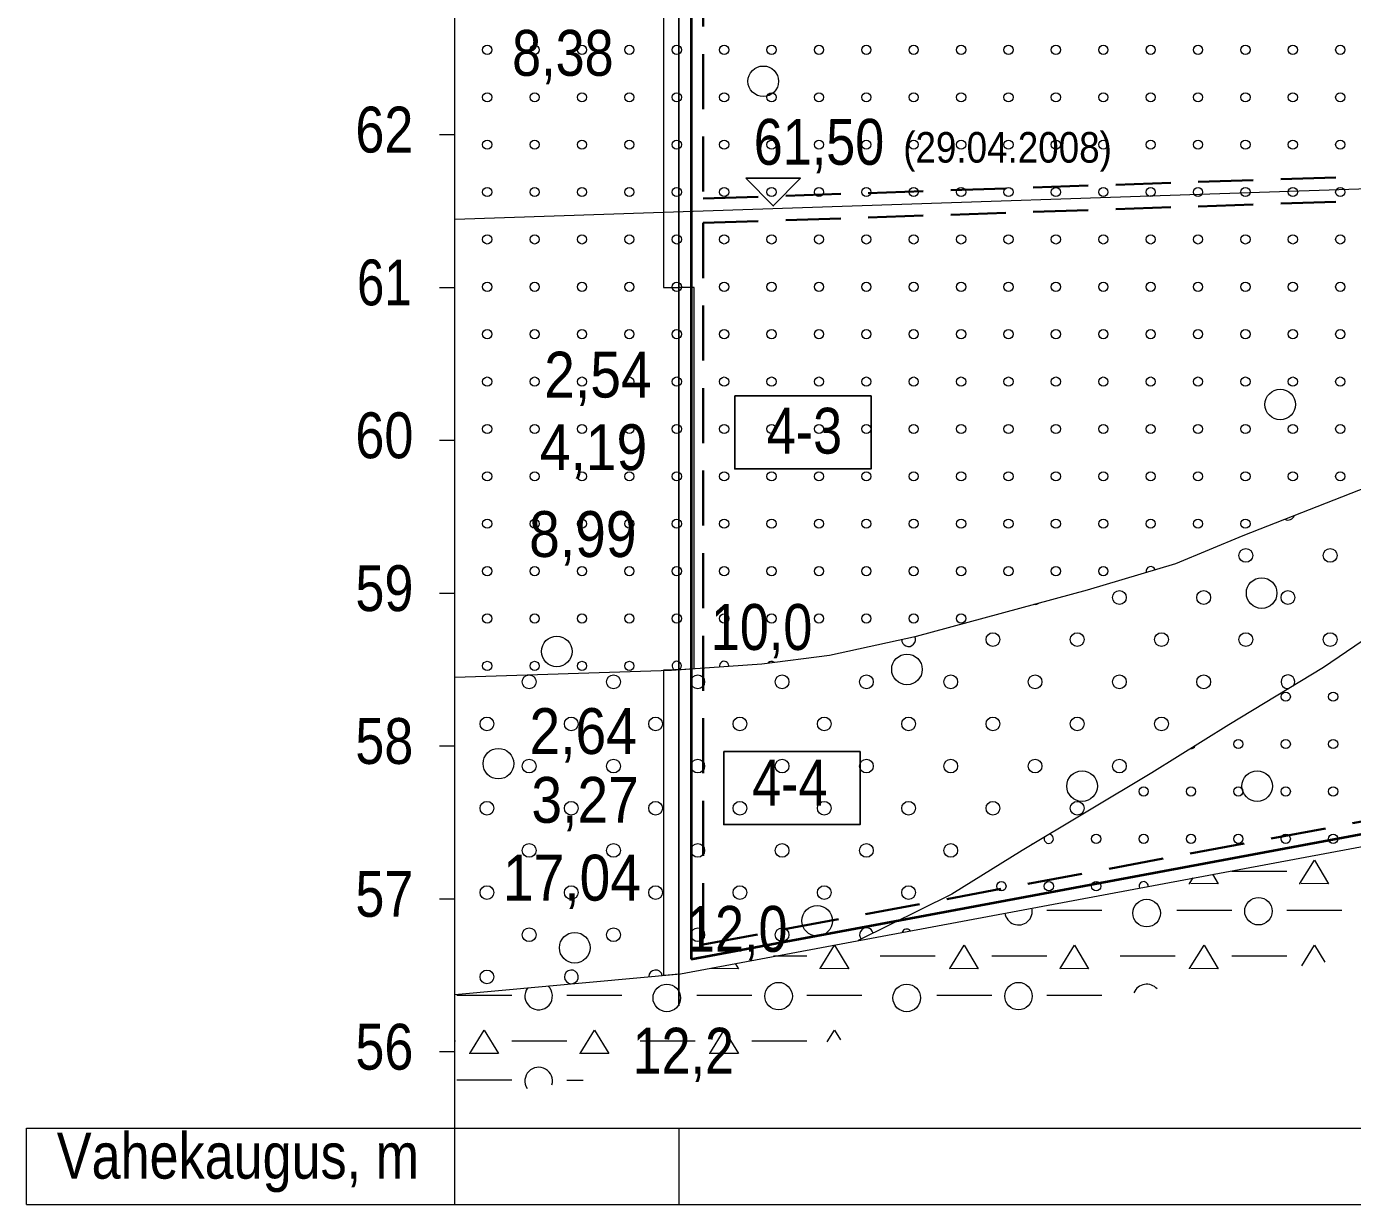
# Model space of a CAD drawing. Extents: x 640121 to 640955, y 6441885 to 6442246.
# Drawn here: x 640607 to 640693.8, y 6442062.2 to 6442139.2 of the extents above; entities that cross this region are included whole.
import ezdxf
from ezdxf.enums import TextEntityAlignment as Align

# ---------------------------------------------------------------- set-up
doc = ezdxf.new("R2010")
doc.units = 0
doc.header["$LTSCALE"] = 1.2
doc.linetypes.add('MEDIUM_DASHED', pattern=[4.5, 3, -1.5])
for name, color, linetype, lineweight in [('30', 7, 'Continuous', 13), ('31', 7, 'Continuous', 13), ('32', 7, 'Continuous', 13), ('33', 7, 'Continuous', 13), ('34', 7, 'Continuous', 25), ('35', 7, 'Continuous', 35), ('42', 7, 'Continuous', 13), ('43', 7, 'Continuous', 13), ('46', 7, 'Continuous', 13), ('47', 7, 'Continuous', 13)]:
    doc.layers.add(name, color=color, linetype=linetype, lineweight=lineweight)

msp = doc.modelspace()

# ---------------------------------------------------------------- linework, layer by layer
at = {"layer": '30'}
for p, q in [((640635.03, 6442062.16), (640635.03, 6442212.16)), ((640634.03, 6442132.16), (640635.03, 6442132.16)), ((640634.03, 6442122.16), (640635.03, 6442122.16)), ((640634.03, 6442112.16), (640635.03, 6442112.16)), ((640634.03, 6442102.16), (640635.03, 6442102.16)), ((640634.03, 6442092.16), (640635.03, 6442092.16)), ((640634.03, 6442082.16), (640635.03, 6442082.16)), ((640634.03, 6442072.16), (640635.03, 6442072.16)), ((640649.69, 6442067.16), (640649.69, 6442062.16)), ((640607.02, 6442062.16), (640933.07, 6442062.16))]:
    msp.add_line(p, q, dxfattribs=at)
msp.add_lwpolyline([(640607.02, 6442062.16), (640607.02, 6442067.16), (640933.07, 6442067.16)], dxfattribs=at)
at = {"layer": '31'}
for points in [[(640768.87, 6442162.69), (640757.51, 6442156.14), (640750.7, 6442151.38), (640740.57, 6442142.18), (640734.45, 6442136.52), (640730.23, 6442132.58), (640726.39, 6442128.73), (640721.62, 6442123.48), (640717.7, 6442119.38), (640711.91, 6442113.06), (640707.64, 6442108.99), (640702.12, 6442104.54), (640697.95, 6442101.43), (640691.86, 6442097.28), (640685.68, 6442093.53), (640680.63, 6442090.4), (640672.14, 6442085.32), (640667.54, 6442082.46), (640661.43, 6442079.43)], [(640635.03, 6442075.9), (640649.8, 6442077.26), (640785.83, 6442102.65), (640874.62, 6442120.89), (640920.62, 6442127.04), (640933.07, 6442127.28)], [(640635.03, 6442096.66), (640649.21, 6442097.12), (640655.12, 6442097.54), (640659.54, 6442098.09), (640665.24, 6442099.34), (640676.43, 6442102.37), (640682.2, 6442104.09), (640686.61, 6442105.93), (640696.91, 6442109.95), (640705.39, 6442113.44), (640709.68, 6442115.54), (640714.26, 6442118.46), (640721.62, 6442123.48)]]:
    msp.add_lwpolyline(points, dxfattribs=at)
at = {"layer": '32', "lineweight": 25}
msp.add_line((640649.69, 6442197.16), (640649.69, 6442075.16), dxfattribs=at)
at = {"layer": '33'}
for points in [[(640648.69, 6442157.16), (640648.69, 6442122.16), (640649.69, 6442122.16), (640649.69, 6442157.16)], [(640650.69, 6442097.23), (640650.69, 6442122.16), (640649.69, 6442122.16), (640649.69, 6442097.16), (640649.77, 6442097.16)], [(640648.69, 6442097.11), (640648.69, 6442077.16), (640648.76, 6442077.16), (640649.69, 6442077.25), (640649.69, 6442097.16), (640649.21, 6442097.12)]]:
    msp.add_lwpolyline(points, close=True, dxfattribs=at)
at = {"layer": '33', "lineweight": 25}
for points in [[(640653.35, 6442115.06), (640662.27, 6442115.06), (640662.27, 6442110.28), (640653.35, 6442110.28)], [(640652.63, 6442091.79), (640661.55, 6442091.79), (640661.55, 6442087.01), (640652.63, 6442087.01)]]:
    msp.add_lwpolyline(points, close=True, dxfattribs=at)
at = {"layer": '34', "lineweight": 13}
msp.add_lwpolyline([(640635.03, 6442126.63), (640785.8, 6442131.67), (640874.6, 6442135.86), (640933.07, 6442137.4)], dxfattribs=at)
at = {"layer": '34'}
msp.add_lwpolyline([(640654.08, 6442129.3), (640655.87, 6442127.49), (640657.65, 6442129.3)], close=True, dxfattribs=at)
at = {"layer": '35', "lineweight": 40}
msp.add_line((640650.49, 6442192.47), (640650.49, 6442078.2), dxfattribs=at)
at = {"layer": '35', "linetype": 'MEDIUM_DASHED'}
for p, q in [((640651.29, 6442191.42), (640651.29, 6442127.97)), ((640651.29, 6442126.37), (640651.29, 6442079.17))]:
    msp.add_line(p, q, dxfattribs=at)
for points in [[(640651.29, 6442127.97), (640785.76, 6442132.47), (640872.99, 6442136.59)], [(640651.29, 6442126.37), (640785.83, 6442130.88), (640872.99, 6442134.99)], [(640651.29, 6442079.17), (640785.52, 6442104.22), (640872.99, 6442122.19)]]:
    msp.add_lwpolyline(points, dxfattribs=at)
at = {"layer": '35', "lineweight": 40}
msp.add_lwpolyline([(640650.49, 6442078.2), (640785.68, 6442103.44), (640873.79, 6442121.54)], dxfattribs=at)
at = {"layer": '42'}
for centre in [(640686.781, 6442104.627), (640692.297, 6442104.627), (640678.508, 6442101.87), (640684.024, 6442101.87), (640689.539, 6442101.87), (640670.235, 6442099.112), (640675.751, 6442099.112), (640681.266, 6442099.112), (640686.781, 6442099.112), (640692.297, 6442099.112), (640639.9, 6442096.354), (640645.416, 6442096.354), (640650.931, 6442096.354), (640656.446, 6442096.354), (640661.962, 6442096.354), (640667.477, 6442096.354), (640672.993, 6442096.354), (640678.508, 6442096.354), (640684.024, 6442096.354), (640637.142, 6442093.597), (640642.658, 6442093.597), (640648.173, 6442093.597), (640653.689, 6442093.597), (640659.204, 6442093.597), (640664.72, 6442093.597), (640670.235, 6442093.597), (640675.751, 6442093.597), (640681.266, 6442093.597), (640639.9, 6442090.839), (640645.416, 6442090.839), (640650.931, 6442090.839), (640656.446, 6442090.839), (640661.962, 6442090.839), (640667.477, 6442090.839), (640672.993, 6442090.839), (640678.508, 6442090.839), (640637.142, 6442088.081), (640642.658, 6442088.081), (640648.173, 6442088.081), (640653.689, 6442088.081), (640659.204, 6442088.081), (640664.72, 6442088.081), (640670.235, 6442088.081), (640675.751, 6442088.081), (640639.9, 6442085.323), (640645.416, 6442085.323), (640650.931, 6442085.323), (640656.446, 6442085.323), (640661.962, 6442085.323), (640667.477, 6442085.323), (640637.142, 6442082.566), (640642.658, 6442082.566), (640648.173, 6442082.566), (640653.689, 6442082.566), (640659.204, 6442082.566), (640664.72, 6442082.566), (640639.9, 6442079.808), (640645.416, 6442079.808), (640650.931, 6442079.808), (640656.446, 6442079.808), (640637.142, 6442077.05)]:
    msp.add_circle(centre, 0.45, dxfattribs=at)
for centre, start, end in [((640689.539, 6442107.385), 240.92765, 341.71288), ((640672.993, 6442101.87), 261.25471, 309.04747), ((640664.72, 6442099.112), 177.54593, 27.22654), ((640689.539, 6442096.354), 324.81171, 277.61735), ((640672.993, 6442085.323), 105.74286, 136.09246), ((640661.962, 6442079.808), 13.29816, 219.42595), ((640642.658, 6442077.05), 283.67298, 266.84706), ((640648.173, 6442077.05), 12.98319, 177.53686)]:
    msp.add_arc(centre, 0.45, start, end, dxfattribs=at)
at = {"layer": '43'}
for centre in [(640637.157, 6442137.695), (640640.257, 6442137.695), (640643.357, 6442137.695), (640646.457, 6442137.695), (640649.557, 6442137.695), (640652.657, 6442137.695), (640655.757, 6442137.695), (640658.857, 6442137.695), (640661.957, 6442137.695), (640665.057, 6442137.695), (640668.157, 6442137.695), (640671.257, 6442137.695), (640674.357, 6442137.695), (640677.457, 6442137.695), (640680.557, 6442137.695), (640683.657, 6442137.695), (640686.757, 6442137.695), (640689.857, 6442137.695), (640692.957, 6442137.695), (640637.157, 6442134.595), (640640.257, 6442134.595), (640643.357, 6442134.595), (640646.457, 6442134.595), (640649.557, 6442134.595), (640652.657, 6442134.595), (640655.757, 6442134.595), (640658.857, 6442134.595), (640661.957, 6442134.595), (640665.057, 6442134.595), (640668.157, 6442134.595), (640671.257, 6442134.595), (640674.357, 6442134.595), (640677.457, 6442134.595), (640680.557, 6442134.595), (640683.657, 6442134.595), (640686.757, 6442134.595), (640689.857, 6442134.595), (640692.957, 6442134.595), (640637.157, 6442131.495), (640640.257, 6442131.495), (640643.357, 6442131.495), (640646.457, 6442131.495), (640649.557, 6442131.495), (640652.657, 6442131.495), (640655.757, 6442131.495), (640658.857, 6442131.495), (640661.957, 6442131.495), (640665.057, 6442131.495), (640668.157, 6442131.495), (640671.257, 6442131.495), (640674.357, 6442131.495), (640677.457, 6442131.495), (640680.557, 6442131.495), (640683.657, 6442131.495), (640686.757, 6442131.495), (640689.857, 6442131.495), (640692.957, 6442131.495), (640637.157, 6442128.395), (640640.257, 6442128.395), (640643.357, 6442128.395), (640646.457, 6442128.395), (640649.557, 6442128.395), (640652.657, 6442128.395), (640655.757, 6442128.395), (640658.857, 6442128.395), (640661.957, 6442128.395), (640665.057, 6442128.395), (640668.157, 6442128.395), (640671.257, 6442128.395), (640674.357, 6442128.395), (640677.457, 6442128.395), (640680.557, 6442128.395), (640683.657, 6442128.395), (640686.757, 6442128.395), (640689.857, 6442128.395), (640692.957, 6442128.395), (640637.157, 6442125.295), (640640.257, 6442125.295), (640643.357, 6442125.295), (640646.457, 6442125.295), (640649.557, 6442125.295), (640652.657, 6442125.295), (640655.757, 6442125.295), (640658.857, 6442125.295), (640661.957, 6442125.295), (640665.057, 6442125.295), (640668.157, 6442125.295), (640671.257, 6442125.295), (640674.357, 6442125.295), (640677.457, 6442125.295), (640680.557, 6442125.295), (640683.657, 6442125.295), (640686.757, 6442125.295), (640689.857, 6442125.295), (640692.957, 6442125.295), (640637.157, 6442122.195), (640640.257, 6442122.195), (640643.357, 6442122.195), (640646.457, 6442122.195), (640649.557, 6442122.195), (640652.657, 6442122.195), (640655.757, 6442122.195), (640658.857, 6442122.195), (640661.957, 6442122.195), (640665.057, 6442122.195), (640668.157, 6442122.195), (640671.257, 6442122.195), (640674.357, 6442122.195), (640677.457, 6442122.195), (640680.557, 6442122.195), (640683.657, 6442122.195), (640686.757, 6442122.195), (640689.857, 6442122.195), (640692.957, 6442122.195), (640637.157, 6442119.095), (640640.257, 6442119.095), (640643.357, 6442119.095), (640646.457, 6442119.095), (640649.557, 6442119.095), (640652.657, 6442119.095), (640655.757, 6442119.095), (640658.857, 6442119.095), (640661.957, 6442119.095), (640665.057, 6442119.095), (640668.157, 6442119.095), (640671.257, 6442119.095), (640674.357, 6442119.095), (640677.457, 6442119.095), (640680.557, 6442119.095), (640683.657, 6442119.095), (640686.757, 6442119.095), (640689.857, 6442119.095), (640692.957, 6442119.095), (640637.157, 6442115.995), (640640.257, 6442115.995), (640643.357, 6442115.995), (640646.457, 6442115.995), (640649.557, 6442115.995), (640652.657, 6442115.995), (640655.757, 6442115.995), (640658.857, 6442115.995), (640661.957, 6442115.995), (640665.057, 6442115.995), (640668.157, 6442115.995), (640671.257, 6442115.995), (640674.357, 6442115.995), (640677.457, 6442115.995), (640680.557, 6442115.995), (640683.657, 6442115.995), (640686.757, 6442115.995), (640689.857, 6442115.995), (640692.957, 6442115.995), (640637.157, 6442112.895), (640640.257, 6442112.895), (640643.357, 6442112.895), (640646.457, 6442112.895), (640649.557, 6442112.895), (640652.657, 6442112.895), (640655.757, 6442112.895), (640658.857, 6442112.895), (640661.957, 6442112.895), (640665.057, 6442112.895), (640668.157, 6442112.895), (640671.257, 6442112.895), (640674.357, 6442112.895), (640677.457, 6442112.895), (640680.557, 6442112.895), (640683.657, 6442112.895), (640686.757, 6442112.895), (640689.857, 6442112.895), (640692.957, 6442112.895), (640637.157, 6442109.795), (640640.257, 6442109.795), (640643.357, 6442109.795), (640646.457, 6442109.795), (640649.557, 6442109.795), (640652.657, 6442109.795), (640655.757, 6442109.795), (640658.857, 6442109.795), (640661.957, 6442109.795), (640665.057, 6442109.795), (640668.157, 6442109.795), (640671.257, 6442109.795), (640674.357, 6442109.795), (640677.457, 6442109.795), (640680.557, 6442109.795), (640683.657, 6442109.795), (640686.757, 6442109.795), (640689.857, 6442109.795), (640692.957, 6442109.795), (640637.157, 6442106.695), (640640.257, 6442106.695), (640643.357, 6442106.695), (640646.457, 6442106.695), (640649.557, 6442106.695), (640652.657, 6442106.695), (640655.757, 6442106.695), (640658.857, 6442106.695), (640661.957, 6442106.695), (640665.057, 6442106.695), (640668.157, 6442106.695), (640671.257, 6442106.695), (640674.357, 6442106.695), (640677.457, 6442106.695), (640680.557, 6442106.695), (640683.657, 6442106.695), (640686.757, 6442106.695), (640637.157, 6442103.595), (640640.257, 6442103.595), (640643.357, 6442103.595), (640646.457, 6442103.595), (640649.557, 6442103.595), (640652.657, 6442103.595), (640655.757, 6442103.595), (640658.857, 6442103.595), (640661.957, 6442103.595), (640665.057, 6442103.595), (640668.157, 6442103.595), (640671.257, 6442103.595), (640674.357, 6442103.595), (640677.457, 6442103.595), (640637.157, 6442100.495), (640640.257, 6442100.495), (640643.357, 6442100.495), (640646.457, 6442100.495), (640649.557, 6442100.495), (640652.657, 6442100.495), (640655.757, 6442100.495), (640658.857, 6442100.495), (640661.957, 6442100.495), (640665.057, 6442100.495), (640668.157, 6442100.495), (640637.157, 6442097.395), (640640.257, 6442097.395), (640643.357, 6442097.395), (640646.457, 6442097.395), (640689.394, 6442095.381), (640692.494, 6442095.381), (640686.294, 6442092.281), (640689.394, 6442092.281), (640692.494, 6442092.281), (640680.094, 6442089.181), (640683.194, 6442089.181), (640686.294, 6442089.181), (640689.394, 6442089.181), (640692.494, 6442089.181), (640676.994, 6442086.081), (640680.094, 6442086.081), (640683.194, 6442086.081), (640686.294, 6442086.081), (640689.394, 6442086.081), (640692.494, 6442086.081), (640670.794, 6442082.981), (640673.894, 6442082.981), (640676.994, 6442082.981)]:
    msp.add_circle(centre, 0.3, dxfattribs=at)
for centre, start, end in [((640680.557, 6442103.595), 18.1764, 195.00477), ((640649.557, 6442097.395), 309.21367, 238.91623), ((640652.657, 6442097.395), 359.17976, 188.95013), ((640655.757, 6442097.395), 56.1036, 138.02441), ((640683.194, 6442092.281), 266.53269, 337.04874), ((640673.894, 6442086.081), 155.34846, 86.48687), ((640680.094, 6442082.981), 358.29679, 202.85049), ((640664.594, 6442079.881), 38.24828, 162.899)]:
    msp.add_arc(centre, 0.3, start, end, dxfattribs=at)
at = {"layer": '46'}
for p, q in [((640689.46, 6442083.95), (640685.86, 6442083.95)), ((640677.36, 6442081.39), (640673.76, 6442081.39)), ((640685.86, 6442081.4), (640682.26, 6442081.4)), ((640693.06, 6442081.39), (640689.46, 6442081.39)), ((640658.07, 6442078.4), (640655.89, 6442078.4)), ((640666.47, 6442078.4), (640662.87, 6442078.4)), ((640673.76, 6442078.4), (640670.16, 6442078.4)), ((640682.16, 6442078.4), (640678.56, 6442078.4)), ((640689.46, 6442078.4), (640685.86, 6442078.4)), ((640638.77, 6442075.84), (640635.17, 6442075.84)), ((640645.97, 6442075.84), (640642.37, 6442075.84)), ((640654.47, 6442075.84), (640650.87, 6442075.84)), ((640661.67, 6442075.84), (640658.07, 6442075.84)), ((640670.16, 6442075.84), (640666.56, 6442075.84)), ((640677.36, 6442075.84), (640673.76, 6442075.84)), ((640635.08, 6442072.85), (640635.03, 6442072.85)), ((640642.37, 6442072.84), (640638.77, 6442072.84)), ((640650.77, 6442072.85), (640647.17, 6442072.85)), ((640658.07, 6442072.84), (640654.47, 6442072.84)), ((640638.77, 6442070.29), (640635.17, 6442070.29)), ((640643.44, 6442070.28), (640642.37, 6442070.28))]:
    msp.add_line(p, q, dxfattribs=at)
for points in [[(640690.32, 6442083.12), (640690.32, 6442083.15), (640691.27, 6442084.68), (640692.2, 6442083.14), (640690.4, 6442083.15)], [(640683.1, 6442083.12), (640683.1, 6442083.15), (640683.33, 6442083.52)], [(640684.6, 6442083.76), (640684.98, 6442083.14), (640683.18, 6442083.15)], [(640658.93, 6442077.57), (640658.93, 6442077.59), (640659.88, 6442079.12), (640660.81, 6442077.58), (640659.01, 6442077.59)], [(640667.4, 6442077.57), (640667.41, 6442077.59), (640668.35, 6442079.12), (640669.28, 6442077.58), (640667.48, 6442077.59)], [(640674.62, 6442077.57), (640674.63, 6442077.59), (640675.57, 6442079.12), (640676.5, 6442077.58), (640674.7, 6442077.59)], [(640683.1, 6442077.57), (640683.1, 6442077.59), (640684.05, 6442079.12), (640684.98, 6442077.58), (640683.18, 6442077.59)], [(640690.44, 6442077.78), (640691.27, 6442079.12), (640691.94, 6442078.02)], [(640651.71, 6442077.57), (640651.71, 6442077.59), (640651.73, 6442077.62)], [(640653.38, 6442077.93), (640653.59, 6442077.58), (640651.79, 6442077.59)], [(640636.01, 6442072.02), (640636.02, 6442072.04), (640636.96, 6442073.57), (640637.89, 6442072.03), (640636.09, 6442072.04)], [(640643.23, 6442072.02), (640643.24, 6442072.04), (640644.18, 6442073.57), (640645.11, 6442072.03), (640643.31, 6442072.04)], [(640651.71, 6442072.02), (640651.71, 6442072.04), (640652.66, 6442073.57), (640653.59, 6442072.03), (640651.79, 6442072.04)], [(640659.4, 6442072.79), (640659.88, 6442073.57), (640660.26, 6442072.93)]]:
    msp.add_lwpolyline(points, dxfattribs=at)
for centre in [(640680.294, 6442081.224), (640687.607, 6442081.346), (640648.904, 6442075.67), (640656.217, 6442075.792), (640664.599, 6442075.67), (640671.912, 6442075.792)]:
    msp.add_circle(centre, 0.9, dxfattribs=at)
for centre, start, end in [((640671.912, 6442081.346), 187.91797, 13.22931), ((640640.522, 6442075.792), 142.4118, 48.10824), ((640680.294, 6442075.67), 40.87359, 157.37643), ((640640.522, 6442070.238), 344.07193, 212.18828)]:
    msp.add_arc(centre, 0.9, start, end, dxfattribs=at)
at = {"layer": '47'}
for centre in [(640655.216, 6442135.64), (640689.033, 6442114.494), (640687.816, 6442102.159), (640641.707, 6442098.341), (640664.615, 6442097.166), (640637.889, 6442090.999), (640676.069, 6442089.53), (640687.523, 6442089.53), (640658.741, 6442080.719), (640642.881, 6442078.957)]:
    msp.add_circle(centre, 1, dxfattribs=at)

# ---------------------------------------------------------------- texts
at = {"layer": '30'}
for s, width, p in [('62', 0.85, (640630.43, 6442130.98)), ('61', 0.8, (640630.425, 6442120.98)), ('60', 0.85, (640630.43, 6442110.98)), ('59', 0.85, (640630.43, 6442100.98)), ('58', 0.85, (640630.425, 6442090.98)), ('57', 0.85, (640630.43, 6442080.98)), ('56', 0.85, (640630.43, 6442070.98)), ('Vahekaugus, m', 0.85, (640620.85, 6442063.85))]:
    msp.add_text(s, height=3, dxfattribs=dict(at, width=width)).set_placement(p, align=Align.CENTER)
at = {"layer": '32'}
for s, width, p in [('8,38', 0.85, (640642.105, 6442136)), ('2,54', 0.9, (640644.4, 6442114.95)), ('8,99', 0.9, (640643.41, 6442104.52)), ('10,0', 0.85, (640655.105, 6442098.44)), ('2,64', 0.9, (640643.435, 6442091.63)), ('17,04', 0.9, (640642.7, 6442082.04)), ('12,0', 0.85, (640653.48, 6442078.69)), ('12,2', 0.85, (640649.985, 6442070.72))]:
    msp.add_text(s, height=3, dxfattribs=dict(at, width=width)).set_placement(p, align=Align.CENTER)
at = {"layer": '33'}
for s, width, p in [('4-3', 0.85, (640657.91, 6442111.28)), ('4,19', 0.9, (640644.11, 6442110.2)), ('4-4', 0.85, (640656.95, 6442088.25)), ('3,27', 0.9, (640643.56, 6442087.13))]:
    msp.add_text(s, height=3, dxfattribs=dict(at, width=width)).set_placement(p, align=Align.CENTER)
at = {"layer": '34'}
for s, height, width, p in [('61,50', 3, 0.85, (640658.86, 6442130.18)), ('(29.04.2008)', 2, 0.9, (640671.195, 6442130.32))]:
    msp.add_text(s, height=height, dxfattribs=dict(at, width=width)).set_placement(p, align=Align.CENTER)

doc.saveas('drawing.dxf')
